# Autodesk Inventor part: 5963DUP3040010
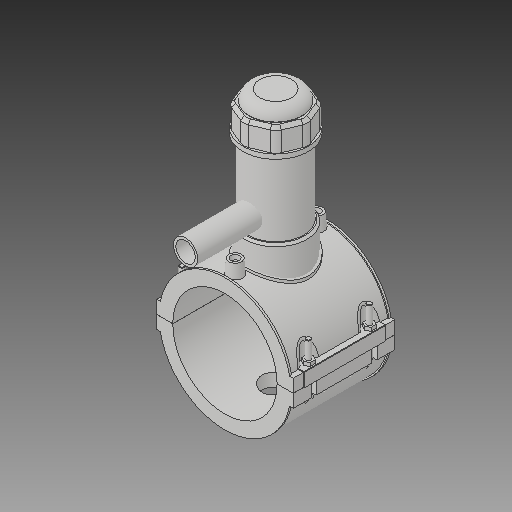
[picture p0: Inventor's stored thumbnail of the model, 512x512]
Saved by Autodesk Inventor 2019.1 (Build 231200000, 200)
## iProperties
Created: 2017-07
Part Number: 5963DUP3040010
Material: Generic
Description: PLASSON TAPPING SADDLE 4''DIPS x 1''CTS
Document SubType Name: Modeling
Designer: KIM
Density: 1 g/cm^3
Appearance: Default
Author: KIM
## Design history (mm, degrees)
derived "5963DBP_5963BUP.ipt"
feature "Solid1::5963DBP_5963BUP.ipt"
feature "Solid2::5963DBP_5963BUP.ipt"
feature "Solid3::5963DBP_5963BUP.ipt"
tag "TaggingFeature1"
body "Solid1"
body "Solid2"
body "Solid3"
other parameters: "d0" = 121.3, "d2" = 159.004, "d3" = 30.325, "d4" = 118.11, "d5" = 0, "d6" = 0.1, "d8" = 0, "d19" = 6, "d20" = 6, "d21" = 70.866, "d23" = 0, "d24" = 35.433, "d26" = 0, "d27" = 3, "d28" = 3, "d29" = 3, "d30" = 40.43333, "d31" = 6, "d32" = 0, "d33" = 0, "d34" = 0.6, "d40" = 78.21424, "d41" = 76.419, "d43" = 0, "d45" = 0, "d47" = 146.072, "d70" = 15, "d72" = 0, "d73" = 6, "d75" = 5, "d76" = 0, "d77" = 6.065, "d78" = 90.65, "d79" = 15, "d80" = 47.244, "d82" = 5 deg, "d84" = 4, "d85" = 14, "d86" = 0, "d87" = 3, "d88" = 0, "d89" = 1, "d90" = 1, "d91" = 94.488, "d92" = 0, "d93" = 0.5, "d94" = 63.84211, "d96" = 153.42024, "d97" = 2.3622, "d98" = 0, "d120" = 140 deg, "d121" = 24.228, "d122" = 20 deg, "d123" = 300.824, "d124" = 90.2472, "d126" = 0, "d143" = 124.939, "d145" = 22.39385, "d149" = 1.8195, "d150" = 24.63323, "d153" = 118.11, "d154" = 0, "d156" = 75.206, "d157" = 160 deg, "d159" = 5.8224, "d161" = 1.8195, "d162" = 70.866, "d163" = 0, "d164" = 60.65, "d167" = 12.13, "d168" = 73.37171, "d170" = 3.4335, "d172" = 0, "d173" = 1, "d175" = 60.65, "d176" = 20 deg, "d177" = 8.491, "d178" = 29.112, "d180" = 0, "d183" = 11.6448, "d184" = 6.7928, "d185" = 38.38575, "d186" = 38.38575, "d187" = 75.206, "d188" = 8.7336, "d189" = 8.491, "d190" = 0, "d191" = 112.809, "d193" = 7.3248, "d194" = 4.13385, "d195" = 90 deg, "d197" = 0, "d199" = 0, "d200" = 14.556, "d202" = 0, "d203" = 177.038, "d204" = 72.59805, "d205" = 53.4933, "d206" = 64.95615, "d207" = 132.7785, "d208" = 138.08964, "d209" = 164.64534, "d210" = 65.72034, "d211" = 76.419, "d212" = 61.1352, "d213" = 45.7191, "d216" = 0, "d217" = 12.13, "d218" = 12.13, "d219" = 2.426, "d222" = 121.3, "d224" = 0, "d225" = 65.024, "d226" = 28.45, "d227" = 22.76, "d228" = 104.902, "d230" = 3.639, "d_" = 121.3, "B_" = 159.004, "L_" = 118.11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
